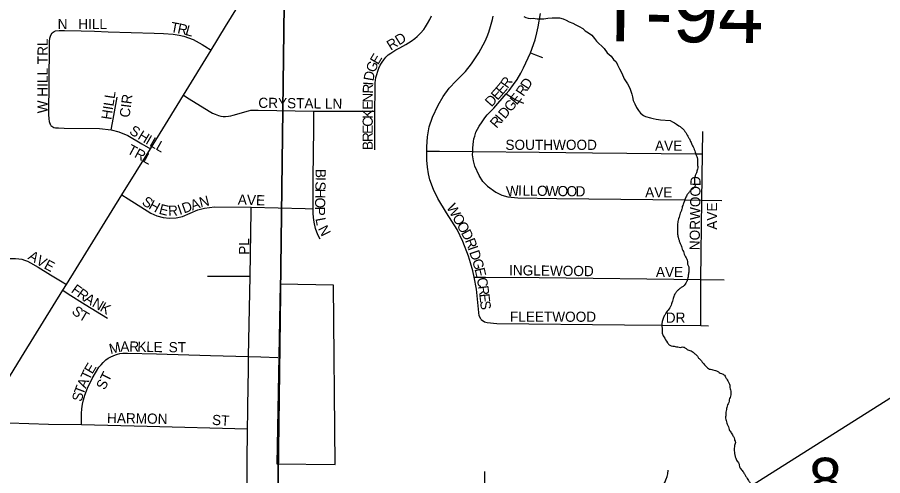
# Model space of a CAD drawing. Extents: x 1587405 to 1714697, y 1028970 to 1155083.
# Drawn here: x 1654947 to 1659199, y 1116017 to 1118270 of the extents above; entities that cross this region are included whole.
import ezdxf

# ---------------------------------------------------------------- set-up
doc = ezdxf.new("R2010")
doc.units = 0
for name, color, linetype in [('GM_X_City_Street', 7, 'Continuous'), ('GM_X_City_Street_Text', 7, 'Continuous'), ('GM_X_Corporation', 7, 'Continuous'), ('GM_X_Minor_River', 7, 'Continuous'), ('GM_X_Rail_Line', 7, 'Continuous'), ('GM_X_Section', 7, 'Continuous'), ('GM_X_Section_Text', 7, 'Continuous'), ('GM_X_Township_Road_Text', 7, 'Continuous')]:
    doc.layers.add(name, color=color, linetype=linetype)

msp = doc.modelspace()

# ---------------------------------------------------------------- linework, layer by layer
at = {"layer": 'GM_X_City_Street'}
for points in [[(1655899.8, 1118108.8), (1655971, 1118224.9), (1656160, 1118532), (1656237.9, 1118657.3), (1656261.9, 1118696.1)], [(1656704.6, 1117808), (1656705.2, 1117909.3), (1656705.6, 1117936.3), (1656706, 1117946.8), (1656707.4, 1117960.7), (1656709.6, 1117973.2), (1656713.3, 1117988.9), (1656718, 1118004.4), (1656723.8, 1118019.4), (1656730.9, 1118033.8), (1656739.9, 1118048.5), (1656748.4, 1118060.7), (1656758.1, 1118073), (1656770, 1118084.6), (1656782, 1118094.1), (1656806.8, 1118109.1), (1656827.5, 1118120.3), (1656855.5, 1118135.1), (1656870.2, 1118144.2), (1656881.8, 1118151.8), (1656900.5, 1118165.8), (1656911.3, 1118174.6), (1656928, 1118191.4), (1656944.2, 1118209.6), (1656952.8, 1118222.1), (1656963.4, 1118239.2), (1656973.9, 1118259.5), (1656982, 1118277.4)], [(1656959, 1117611.9), (1656958.9, 1117633.5), (1656962.5, 1117682.8), (1656971.7, 1117731.5), (1656986.9, 1117778.7), (1657014.7, 1117838.5), (1657040.3, 1117880.9), (1657069.8, 1117920.5), (1657103.3, 1117957), (1657149, 1118003.3), (1657179.7, 1118040.7), (1657215.6, 1118094.8), (1657246.3, 1118151.8), (1657256.3, 1118176), (1657264.1, 1118196.9), (1657272.3, 1118224), (1657281.7, 1118258.3), (1657285.2, 1118275.3)], [(1657468.9, 1118095), (1657491.2, 1118158.2), (1657500.5, 1118193.5), (1657507, 1118222.4), (1657517.8, 1118287.5)], [(1655111.9, 1117738.4), (1655105.1, 1117756.5), (1655103.3, 1117772.8), (1655102.3, 1117790.4), (1655104.9, 1118123.4), (1655105.1, 1118135.5), (1655105.4, 1118151.3), (1655106.7, 1118166.8), (1655111.7, 1118181.2), (1655118.9, 1118193)], [(1655118.9, 1118193), (1655128, 1118200.3), (1655134.4, 1118202.6), (1655152.9, 1118205.5), (1655180, 1118204.8), (1655261.6, 1118203), (1655326.7, 1118200.9), (1655393.3, 1118198.1), (1655619.4, 1118192.3), (1655665.5, 1118190.1), (1655713.9, 1118186.5), (1655742.9, 1118182), (1655765.5, 1118176.2), (1655812.2, 1118159.9), (1655855.6, 1118136.4), (1655869.4, 1118127.8), (1655899.8, 1118108.8)], [(1655764, 1117887.1), (1655899.8, 1118108.8)], [(1657349.9, 1117893.5), (1657363.8, 1117909.7), (1657385.8, 1117938.9), (1657402.7, 1117963.1), (1657421, 1117994.9), (1657435.1, 1118020.8), (1657468.9, 1118095)], [(1657468.9, 1118095), (1657493.6, 1118085.2), (1657528, 1118071.6)], [(1655408.3, 1117716.1), (1655414.6, 1117750.3), (1655438.1, 1117876.3)], [(1655601.6, 1117623.7), (1655688.1, 1117763.4), (1655764, 1117887.1)], [(1655764, 1117887.1), (1655791.6, 1117869.7), (1655889.3, 1117808.3), (1655906.2, 1117799.2), (1655919.5, 1117793.3), (1655935.7, 1117787), (1655946.9, 1117783.9), (1655958.8, 1117782.1), (1655970.7, 1117782.1), (1655984.4, 1117783.5), (1655995.9, 1117785.6), (1656008.2, 1117789.1), (1656083.1, 1117810), (1656094.8, 1117812.7), (1656107, 1117813.3), (1656131.6, 1117813.5), (1656404.2, 1117808.9)], [(1657184.7, 1117610.6), (1657185.1, 1117627.9), (1657188.2, 1117658.4), (1657190.9, 1117671.7), (1657194.5, 1117685), (1657200.7, 1117704.6), (1657207.7, 1117720.6), (1657216, 1117735.2), (1657230.8, 1117756.3), (1657243.8, 1117774.7), (1657255.9, 1117789.9), (1657270.6, 1117804.6), (1657288.5, 1117822.3), (1657349.9, 1117893.5)], [(1657349.9, 1117893.5), (1657379.7, 1117874.6), (1657397.2, 1117863.4), (1657414, 1117855.2), (1657433.6, 1117847.3)], [(1656401.5, 1117328.5), (1656401.3, 1117479.5), (1656403.9, 1117722.4), (1656404.2, 1117808.9)], [(1656404.2, 1117808.9), (1656658.4, 1117808.2), (1656704.6, 1117808)], [(1656703.6, 1117617.7), (1656704.6, 1117808)], [(1655111.9, 1117738.4), (1655126.5, 1117727.9), (1655135.7, 1117726.3), (1655150, 1117726.2), (1655177.1, 1117725.5), (1655350.6, 1117722.8), (1655408.3, 1117716.1)], [(1655408.3, 1117716.1), (1655445.7, 1117706.8), (1655490.4, 1117688.3), (1655559.8, 1117647.9), (1655601.6, 1117623.7)], [(1658313.5, 1117597.9), (1658314.8, 1117707.9)], [(1655460.8, 1117396.5), (1655601.6, 1117623.7)], [(1656959, 1117611.9), (1656989.4, 1117612.2), (1657022.1, 1117612.4), (1657184.7, 1117610.6)], [(1657192.2, 1116992.9), (1657185.2, 1117024), (1657174, 1117063.6), (1657164.6, 1117095.4), (1657136.8, 1117168.1), (1657107.9, 1117226.1), (1657056.6, 1117309.2), (1657014.1, 1117379.4), (1656992.6, 1117423.9), (1656974.6, 1117470.1), (1656967.2, 1117499.5), (1656962.3, 1117532.4), (1656959.2, 1117567.7), (1656959, 1117611.9)], [(1657235.3, 1117462.4), (1657216.2, 1117492.3), (1657195.4, 1117538.3), (1657188.5, 1117564), (1657184.1, 1117593.4), (1657184.7, 1117610.6)], [(1657184.7, 1117610.6), (1657512, 1117607.1), (1657773.3, 1117604.1), (1658280.1, 1117598.3), (1658313.5, 1117597.9)], [(1658310.9, 1117370.9), (1658313.5, 1117597.9)], [(1657235.3, 1117462.4), (1657258.2, 1117439.5), (1657298.2, 1117411), (1657327.2, 1117396.2), (1657358.1, 1117386.8), (1657406.9, 1117382), (1657597.9, 1117379.4), (1658226.3, 1117371.8), (1658310.9, 1117370.9)], [(1655188.4, 1116956.7), (1655460.8, 1117396.5)], [(1655460.8, 1117396.5), (1655492.2, 1117376.9), (1655603.5, 1117307.4), (1655632.7, 1117294.5), (1655663.8, 1117286.3), (1655695.7, 1117283.1), (1655727.9, 1117284.6), (1655759.2, 1117291.3), (1655834.7, 1117323.1), (1655867, 1117332.4), (1655916.7, 1117338.4), (1656096.1, 1117336.1)], [(1658306.3, 1116981.3), (1658310.9, 1117370.9)], [(1658310.9, 1117370.9), (1658408.2, 1117369.8)], [(1656091, 1116997.4), (1656095.8, 1117319.3), (1656096.1, 1117336.1)], [(1656096.1, 1117336.1), (1656361.4, 1117329.5), (1656401.5, 1117328.5)], [(1656434.7, 1117178.5), (1656423.5, 1117200.6), (1656413, 1117231.6), (1656406, 1117262.5), (1656402.6, 1117286.1), (1656401, 1117306.3), (1656401.5, 1117328.5)], [(1654755.9, 1117088.6), (1654873.6, 1117085), (1654910, 1117085), (1654939.4, 1117084), (1654955.5, 1117082.8), (1654969.4, 1117080.8), (1654983.1, 1117076.8), (1654997, 1117071.1), (1655011.7, 1117063.6), (1655050.7, 1117041.6), (1655110.1, 1117003.9), (1655167.4, 1116969.4), (1655188.4, 1116956.7)], [(1655881.4, 1116997.3), (1655904.1, 1116997.5), (1656000.8, 1116997.5), (1656091, 1116997.4)], [(1656084.1, 1116603), (1656091, 1116997.4)], [(1657192.2, 1116992.9), (1657230.7, 1116992.9), (1657247.2, 1116992.9), (1657511.4, 1116990.7), (1658306.3, 1116981.3)], [(1657226.3, 1116784.7), (1657217, 1116803.2), (1657203.1, 1116933.6), (1657192.2, 1116992.9)], [(1658305.6, 1116754.2), (1658305.7, 1116797), (1658306.3, 1116981.3)], [(1658306.3, 1116981.3), (1658420.1, 1116980)], [(1655170.7, 1116928), (1655188.4, 1116956.7)], [(1654773.4, 1116282.7), (1654980.4, 1116620.8), (1655170.7, 1116928)], [(1655170.7, 1116928), (1655198, 1116910.6), (1655281, 1116857.6), (1655390.8, 1116791.7)], [(1657226.3, 1116784.7), (1657242, 1116773.7), (1657255.1, 1116769.9), (1657304, 1116765.1), (1657930.8, 1116758.6), (1658305.6, 1116754.2)], [(1658305.6, 1116754.2), (1658342.9, 1116753.7)], [(1655263, 1116268), (1655263, 1116322.6), (1655264.7, 1116346.2), (1655267.3, 1116368), (1655272.4, 1116390.4), (1655279.1, 1116412.4), (1655293.1, 1116447.5), (1655315, 1116495.1), (1655330.9, 1116522.6), (1655348.8, 1116549.5), (1655358.9, 1116562), (1655370, 1116573.8), (1655382.3, 1116586), (1655394, 1116594), (1655407.2, 1116601.8)], [(1655407.2, 1116601.8), (1655429.1, 1116611.1), (1655439.2, 1116614), (1655450.9, 1116617.4), (1655465.9, 1116619.3), (1655488.6, 1116619.4), (1655631.8, 1116615), (1655896.1, 1116607), (1656084.1, 1116603)], [(1656078.6, 1116247.7), (1656079.4, 1116329.6), (1656079.5, 1116359.1), (1656082.6, 1116539.7), (1656084.1, 1116603)], [(1656084.1, 1116603), (1656144.2, 1116601.1), (1656227.4, 1116597.2)], [(1654773.4, 1116282.7), (1654808.5, 1116279.8), (1655100.5, 1116269.7), (1655263, 1116268)], [(1655263, 1116268), (1655585.2, 1116260.9), (1656078.6, 1116247.7)], [(1656076.9, 1115919.5), (1656077.1, 1116082.3), (1656078.6, 1116247.7)], [(1657244.2, 1115907), (1657245.1, 1116037.1)], [(1657832.1, 1115773.7), (1658068.7, 1115919.8), (1658083.3, 1115929.3), (1658091.2, 1115935.4), (1658098.7, 1115942.3), (1658106.7, 1115951.9), (1658116.3, 1115964.6), (1658124.7, 1115977.9), (1658129.8, 1115986.1), (1658134, 1115995.8), (1658137.4, 1116004.3), (1658138.2, 1116007.2), (1658140, 1116013.6), (1658142.8, 1116025.2), (1658145.6, 1116044.7)]]:
    msp.add_lwpolyline(points, dxfattribs=at)
at = {"layer": 'GM_X_Corporation'}
msp.add_lwpolyline([(1656222.5, 1116075.4), (1656509.4, 1116072.6), (1656501.7, 1116952.7), (1656239.4, 1116957.5)], close=True, dxfattribs=at)
at = {"layer": 'GM_X_Minor_River'}
for points in [[(1657436.2, 1118274.1), (1657446.1, 1118267.9), (1657458.1, 1118265.6), (1657468.1, 1118263.4), (1657482.2, 1118265.1), (1657502.2, 1118262.7), (1657516.2, 1118262.4), (1657534.3, 1118262.1), (1657554.4, 1118265.7), (1657574.5, 1118267.3), (1657594.6, 1118266.9), (1657610.6, 1118266.6), (1657628.6, 1118262.2), (1657644.5, 1118255.8), (1657658.4, 1118247.5), (1657676.3, 1118241.2), (1657692.2, 1118232.8), (1657708.1, 1118224.5), (1657725.9, 1118214.1), (1657737.8, 1118203.8), (1657753.6, 1118193.5), (1657769.4, 1118181.1), (1657783.1, 1118164.8), (1657792.9, 1118152.6), (1657830.3, 1118115.7), (1657845.9, 1118095.3), (1657865.6, 1118078.9), (1657877.3, 1118062.6), (1657889.1, 1118050.3), (1657896.9, 1118036.1), (1657906.5, 1118015.9), (1657918.1, 1117995.6), (1657929.6, 1117967.3)], [(1657929.6, 1117967.3), (1657945.1, 1117942.9), (1657956.7, 1117920.6), (1657962.4, 1117906.5), (1657966.1, 1117892.3), (1657969.9, 1117878.2), (1657973.5, 1117860.1), (1657981.2, 1117843.9), (1657988.9, 1117825.7), (1657998.6, 1117811.5), (1658008.4, 1117799.2), (1658024.2, 1117786.9), (1658034.1, 1117782.7), (1658058.1, 1117776.2), (1658072, 1117771.9), (1658086, 1117769.6), (1658098, 1117767.3), (1658108, 1117765.1), (1658155.5, 1117763)]]:
    msp.add_lwpolyline(points, dxfattribs=at)
for points in [[(1658155.5, 1117763), (1658197, 1117737), (1658211, 1117726.9), (1658223.1, 1117714.8), (1658239.2, 1117690.7), (1658245.2, 1117678.6), (1658253.3, 1117664.5), (1658261.3, 1117644.4), (1658273.4, 1117620.3), (1658277.4, 1117606.2), (1658283.4, 1117592.1), (1658287.4, 1117580.1), (1658289.4, 1117566), (1658289.4, 1117541.9), (1658291.4, 1117529.8), (1658287.3, 1117517.8), (1658283.3, 1117501.7), (1658277.2, 1117489.6), (1658275.2, 1117477.6), (1658275.2, 1117453.5), (1658277.2, 1117441.4), (1658269.1, 1117429.3), (1658257, 1117419.3), (1658247, 1117409.3), (1658236.9, 1117395.2), (1658228.8, 1117377.2), (1658224.8, 1117367.1), (1658218.7, 1117351), (1658214.7, 1117339), (1658212.6, 1117326.9), (1658206.6, 1117312.9), (1658202.6, 1117300.8), (1658194.5, 1117272.7), (1658190.4, 1117248.6), (1658190.4, 1117236.5), (1658190.4, 1117222.5), (1658190.4, 1117210.4), (1658192.4, 1117198.3), (1658194.4, 1117188.3), (1658198.4, 1117174.2), (1658204.4, 1117158.1), (1658210.4, 1117144), (1658214.5, 1117130), (1658220.5, 1117117.9), (1658224.5, 1117105.8), (1658230.5, 1117091.8), (1658236.6, 1117081.7), (1658240.6, 1117069.6), (1658240.6, 1117055.6), (1658246.6, 1117043.5), (1658246.6, 1117031.4), (1658246.6, 1117017.4), (1658244.5, 1117007.3), (1658242.5, 1116989.2), (1658238.5, 1116975.2), (1658232.4, 1116963.1), (1658212.3, 1116943), (1658200.2, 1116935), (1658190.1, 1116925), (1658180, 1116913), (1658171.9, 1116892.9), (1658167.9, 1116880.8), (1658163.9, 1116866.8), (1658159.8, 1116854.7), (1658144.7, 1116829.6)], [(1658144.7, 1116829.6), (1658130.5, 1116809.7), (1658122.3, 1116793.8), (1658113.9, 1116753.7), (1658115.7, 1116735.7), (1658115.5, 1116717.6), (1658123.4, 1116699.5), (1658142.5, 1116670.5)], [(1658142.5, 1116670.5), (1658153.6, 1116657.7), (1658167.7, 1116653.7), (1658191.8, 1116649.6), (1658205.9, 1116647.6), (1658216, 1116649.6), (1658230.1, 1116643.5), (1658242.2, 1116635.5), (1658262.3, 1116627.4), (1658272.3, 1116619.3), (1658286.4, 1116607.2), (1658294.5, 1116595.2), (1658306.5, 1116583.1), (1658314.6, 1116573), (1658326.7, 1116558.9), (1658338.7, 1116546.9), (1658348.8, 1116540.8), (1658358.9, 1116538.8), (1658370.9, 1116534.7), (1658383, 1116532.7), (1658395.1, 1116524.6), (1658407.2, 1116518.6), (1658421.2, 1116510.5), (1658427.3, 1116500.5), (1658435.3, 1116488.4), (1658441.3, 1116476.3), (1658447.4, 1116462.2), (1658447.4, 1116450.2), (1658451.4, 1116438.1), (1658453.4, 1116426.1), (1658449.3, 1116401.9), (1658445.3, 1116389.9), (1658443.3, 1116375.8), (1658437.2, 1116365.8), (1658433.2, 1116351.7), (1658431.2, 1116341.7), (1658429.1, 1116329.6), (1658429.1, 1116317.6), (1658427.1, 1116305.5), (1658431.1, 1116281.4), (1658435.1, 1116269.3), (1658441.1, 1116257.2), (1658445.1, 1116243.2), (1658455.2, 1116227.1), (1658461.2, 1116217), (1658469.3, 1116202.9), (1658471.3, 1116190.9), (1658475.3, 1116180.8), (1658473.3, 1116170.8), (1658469.2, 1116146.6), (1658473.2, 1116118.5), (1658477.2, 1116102.4), (1658487.3, 1116084.3), (1658493.3, 1116074.2), (1658495.3, 1116062.2), (1658505.4, 1116046.1), (1658517.4, 1116030), (1658525.5, 1116015.9), (1658533.5, 1116003.8), (1658539.5, 1115993.8), (1658549.6, 1115979.7), (1658557.6, 1115967.6), (1658565.7, 1115957.6), (1658575.7, 1115945.5), (1658581.8, 1115933.4), (1658585.8, 1115921.3), (1658585.8, 1115907.2), (1658587.8, 1115895.2), (1658585.7, 1115879.1), (1658583.7, 1115867.1), (1658579.7, 1115855), (1658567.6, 1115830.9), (1658557.5, 1115820.9), (1658541.4, 1115800.8), (1658531.3, 1115788.8), (1658525.2, 1115774.7), (1658519.2, 1115762.7), (1658515.1, 1115750.6), (1658513.1, 1115740.6), (1658511.1, 1115724.5), (1658509.1, 1115712.4), (1658509, 1115698.4), (1658507, 1115686.3), (1658503, 1115672.2), (1658498.9, 1115662.2), (1658490.9, 1115650.1), (1658480.8, 1115638.1), (1658474.8, 1115628.1), (1658470.7, 1115614), (1658466.7, 1115601.9), (1658462.6, 1115591.9), (1658464.6, 1115579.8), (1658468.7, 1115569.8), (1658474.7, 1115553.7), (1658484.7, 1115541.6), (1658496.8, 1115529.5), (1658502.8, 1115517.5)]]:
    msp.add_spline(points, degree=3, dxfattribs=at)
at = {"layer": 'GM_X_Rail_Line'}
msp.add_lwpolyline([(1653567.6, 1112818.9), (1655299.9, 1113913.2), (1659869.5, 1116798.4), (1669730.9, 1123016.6), (1672358.5, 1124671.2), (1681694.7, 1130554.4), (1684436.5, 1132280.4), (1688526.9, 1134851.5), (1688806.9, 1135025.4), (1688953.3, 1135112.6), (1689086.8, 1135186.1), (1689267.7, 1135279.2), (1689470.2, 1135380.7), (1689588.1, 1135442), (1689734, 1135521.9), (1689883.6, 1135607.5), (1690363.1, 1135904.6), (1690749.1, 1136147.9), (1691069.9, 1136367.6)], dxfattribs=at)
at = {"layer": 'GM_X_Section'}
for points in [[(1651255.5, 1118849.2), (1656263, 1118717.5), (1656195.7, 1113439), (1651152, 1113557.3), (1651155.1, 1113643.3)], [(1656263, 1118717.5), (1661639.2, 1118644.5), (1661579.6, 1113384), (1656195.7, 1113439)]]:
    msp.add_lwpolyline(points, close=True, dxfattribs=at)

# ---------------------------------------------------------------- texts
at = {"layer": 'GM_X_City_Street_Text'}
for s, rotation, p in [('N', 0, (1655145.6, 1118211.7)), ('HILL', 0, (1655246.8, 1118211.7)), ('T', 349.2528, (1655697.1, 1118198.3)), ('R', 348.1614, (1655731.4, 1118191.8)), ('L', 344.3998, (1655769.4, 1118183.9)), ('RD', 32.014, (1656782.1, 1118105)), ('W HILL TRL', 90, (1655096.6, 1117797.7)), ('E', 59.0316, (1656719.6, 1118033.3)), ('G', 67.9064, (1656703.9, 1117994.3)), ('D', 79.8945, (1656697, 1117953.7)), ('R', 54.9846, (1657356.8, 1117916.7)), ('D', 57.1564, (1657456.8, 1117911.2)), ('R', 87.887, (1656694.1, 1117894)), ('I', 85.8427, (1656695.6, 1117933.1)), ('E', 48.1359, (1657306.4, 1117858.7)), ('E', 49.427, (1657330.7, 1117885.9)), ('R', 55.9641, (1657434, 1117877.4)), ('HILL', 81.1245, (1655409.1, 1117763.9)), ('CIR', 82.5722, (1655498.7, 1117774.6)), ('CRYSTAL LN', 359.3335, (1656131.4, 1117824.7)), ('N', 89.9253, (1656694.1, 1117850.5)), ('D', 48.1232, (1657277, 1117826)), ('E', 51.2828, (1657401.3, 1117835.9)), ('E', 89.918, (1656694, 1117815.2)), ('G', 49.7565, (1657372, 1117801.2)), ('K', 89.9126, (1656694, 1117771.2)), ('I', 48.9292, (1657328.1, 1117750.8)), ('D', 48.9883, (1657342.6, 1117767.4)), ('C', 89.9228, (1656693.9, 1117731.7)), ('R', 48.9351, (1657302.1, 1117721)), ('S', 328.0381, (1655493.8, 1117700)), ('H', 328.6703, (1655535.3, 1117674.1)), ('E', 89.918, (1656693.9, 1117696.4)), ('I', 329.9547, (1655573.9, 1117650.6)), ('L', 330.2277, (1655593.2, 1117639.4)), ('L', 330.2832, (1655623.8, 1117621.9)), ('R', 89.9228, (1656693.8, 1117656.8)), ('SOUTHWOOD', 0, (1657345.6, 1117617.9)), ('AVE', 0, (1658080.4, 1117613.5)), ('TRL', 331.553, (1655482.9, 1117603.8)), ('B', 89.9271, (1656693.8, 1117617.3)), ('B', 268.9557, (1656413.4, 1117524.7)), ('S', 268.9618, (1656412.3, 1117463)), ('I', 268.9939, (1656412.7, 1117485)), ('NORWOOD', 89.2156, (1658299.8, 1117124.6)), ('H', 268.9508, (1656411.6, 1117427.8)), ('W', 5.6069, (1657351.9, 1117388.5)), ('I', 358.2511, (1657407.1, 1117394)), ('L', 358.9781, (1657429.8, 1117393.4)), ('L', 359.2795, (1657465.3, 1117392.7)), ('O', 359.2568, (1657500.5, 1117392.3)), ('W', 359.2435, (1657544.5, 1117391.7)), ('O', 359.2495, (1657601.7, 1117390.9)), ('O', 359.2495, (1657645.7, 1117390.4)), ('D', 359.2495, (1657689.7, 1117389.8)), ('AVE', 0, (1658032, 1117384.7)), ('S', 326.7722, (1655555.7, 1117352.2)), ('H', 331.2798, (1655588.8, 1117330.8)), ('D', 19.589, (1655766.5, 1117305.1)), ('A', 19.5685, (1655807.9, 1117319.9)), ('N', 14.1317, (1655848.2, 1117334.3)), ('AVE', 358.0261, (1656030.3, 1117349.5)), ('O', 268.9794, (1656410.8, 1117383.8)), ('E', 345.7407, (1655640.2, 1117304.6)), ('R', 0.9083, (1655688.6, 1117294.2)), ('I', 18.8786, (1655745, 1117297.8)), ('P', 269.769, (1656410, 1117339.1)), ('W', 299.5134, (1657054.4, 1117336.1)), ('AVE', 90, (1658385.8, 1117225.7)), ('L', 280.8016, (1656411.8, 1117280.3)), ('O', 299.4982, (1657082.6, 1117286.4)), ('N', 296.7664, (1656423.3, 1117231.3)), ('O', 299.5203, (1657104.3, 1117248)), ('D', 298.1291, (1657125.8, 1117210)), ('PL', 90, (1656086.6, 1117102.5)), ('R', 291.2694, (1657145.9, 1117172.7)), ('A', 328.4627, (1654996.5, 1117084.1)), ('I', 289.2508, (1657160.1, 1117136.2)), ('D', 288.3451, (1657167.3, 1117115.6)), ('V', 330.0765, (1655035.3, 1117060.3)), ('E', 331.6371, (1655074.8, 1117037.6)), ('G', 286.693, (1657181, 1117074.2)), ('E', 283.1748, (1657193.4, 1117032.9)), ('INGLEWOOD', 359.3264, (1657363.3, 1117001.9)), ('AVE', 0, (1658084.8, 1116993.1)), ('C', 280.9195, (1657204.1, 1116986.2)), ('F', 324.2559, (1655208.3, 1116920.9)), ('R', 324.2663, (1655236.9, 1116900.3)), ('R', 277.6974, (1657211.5, 1116948)), ('A', 327.6159, (1655271.6, 1116875.4)), ('E', 276.5152, (1657216.8, 1116909.1)), ('N', 330.444, (1655311.1, 1116850.5)), ('K', 330.5294, (1655349.5, 1116828.7)), ('S', 277.0857, (1657220.8, 1116873.6)), ('S', 318.8475, (1655210.9, 1116818.9)), ('T', 329.4014, (1655245.5, 1116789.9)), ('FLEETWOOD', 0, (1657367.6, 1116773.1)), ('DR', 0, (1658133.2, 1116768.6)), ('M', 13.9258, (1655405.6, 1116613.9)), ('A', 0.9399, (1655453.9, 1116626.2)), ('R', 358.8343, (1655497.4, 1116626.9)), ('K', 358.8668, (1655537, 1116626.1)), ('L', 358.8253, (1655581, 1116625.3)), ('E', 358.8648, (1655616.2, 1116624.5)), ('ST', 0, (1655691.2, 1116623.5)), ('E', 59.0081, (1655315.6, 1116513.2)), ('T', 64.6447, (1655301.2, 1116482.6)), ('ST', 63.4349, (1655376.9, 1116434.6)), ('A', 66.3193, (1655283.7, 1116442.6)), ('T', 69.0762, (1655271.3, 1116410.3)), ('S', 76.1228, (1655263.4, 1116377.7)), ('HARMON', 359.0748, (1655387.9, 1116275.9)), ('ST', 356.4262, (1655902.9, 1116267))]:
    msp.add_text(s, height=50, rotation=rotation, dxfattribs=at).set_placement(p)
at = {"layer": 'GM_X_Section_Text'}
msp.add_text('8', height=221, rotation=0, dxfattribs=at).set_placement((1658835, 1115884))
at = {"layer": 'GM_X_Township_Road_Text'}
msp.add_text('T-94', height=300, rotation=359.2953, dxfattribs=at).set_placement((1657787.1, 1118152.6))

doc.saveas('drawing.dxf')
